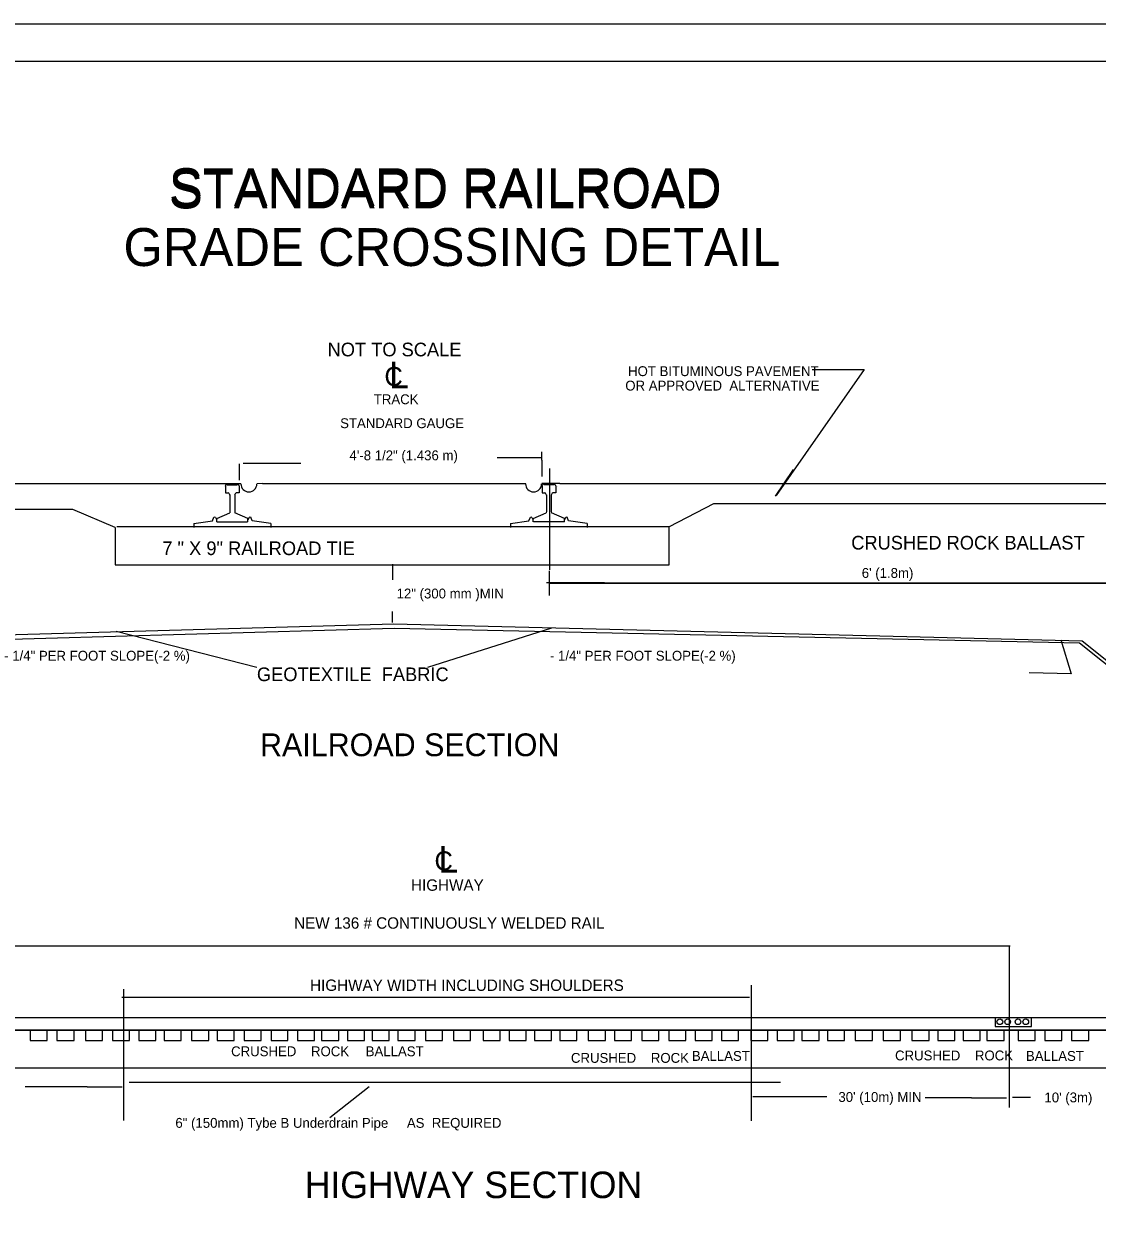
# Model space of a CAD drawing. Extents: x 1100953.69 to 1100956.55, y 386728.28 to 386730.11.
# Drawn here: x 1100954.443 to 1100955.371, y 386729.073 to 386730.11 of the extents above; entities that cross this region are included whole.
import ezdxf

# ---------------------------------------------------------------- set-up
doc = ezdxf.new("R2010")
doc.units = 0
for name, color, linetype in [('BORDER', 7, 'Continuous'), ('Level 1', 7, 'Continuous'), ('Level 33', 7, 'Continuous'), ('ORIG TOPO TEXT', 7, 'Continuous'), ('PLOT BOUNDARY', 7, 'Continuous')]:
    doc.layers.add(name, color=color, linetype=linetype)

msp = doc.modelspace()

# ---------------------------------------------------------------- linework, layer by layer
at = {"layer": 'BORDER'}
msp.add_line((1100956.4931, 386730.0776), (1100953.8264, 386730.0776), dxfattribs=at)
at = {"layer": 'Level 1'}
for p, q in [((1100954.5215, 386729.6745), (1100954.4849, 386729.69)), ((1100954.644, 386729.5534), (1100954.5223, 386729.5846)), ((1100954.7917, 386729.5536), (1100954.8992, 386729.5878)), ((1100954.2952, 386729.3127), (1100955.2955, 386729.3127)), ((1100955.0714, 386729.2788), (1100955.0714, 386729.1613)), ((1100954.5271, 386729.2684), (1100955.07, 386729.2684)), ((1100954.5286, 386729.2752), (1100954.5286, 386729.1615)), ((1100953.8943, 386729.2506), (1100955.7055, 386729.2506)), ((1100954.5336, 386729.1948), (1100955.0969, 386729.1948)), ((1100954.4973, 386729.1908), (1100954.4437, 386729.1908)), ((1100954.7412, 386729.1907), (1100954.707, 386729.1638)), ((1100955.2621, 386729.1812), (1100955.2218, 386729.1812))]:
    msp.add_line(p, q, dxfattribs=at)
for points in [[(1100954.4849, 386729.69), (1100953.8539, 386729.69), (1100953.8539, 386729.7126), (1100953.8539, 386729.7126), (1100954.6144, 386729.7126)], [(1100954.5215, 386729.6745), (1100954.5215, 386729.6423), (1100955.0005, 386729.6423), (1100955.0005, 386729.6749), (1100954.523, 386729.6749)], [(1100955.4278, 386729.5793), (1100955.395, 386729.5465), (1100955.3578, 386729.5763), (1100955.3578, 386729.5763), (1100954.7625, 386729.591), (1100954.1599, 386729.574), (1100954.1361, 386729.5502), (1100954.1075, 386729.5787)], [(1100954.1044, 386729.5735), (1100954.1351, 386729.5442), (1100954.1598, 386729.5701), (1100954.7626, 386729.5873), (1100955.3554, 386729.5746), (1100955.3951, 386729.5429), (1100955.4313, 386729.5776), (1100955.4313, 386729.5776), (1100955.4313, 386729.5776), (1100955.4313, 386729.5776)], [(1100955.7055, 386729.2398), (1100953.8939, 386729.2398), (1100953.8939, 386729.2503)], [(1100953.8943, 386729.2398), (1100953.8943, 386729.2506), (1100953.8943, 386729.2506), (1100955.7062, 386729.2506), (1100955.7062, 386729.2398)], [(1100955.2824, 386729.2507), (1100955.2824, 386729.2429), (1100955.3138, 386729.2429), (1100955.3138, 386729.2506)], [(1100953.8943, 386729.2398), (1100953.8943, 386729.2398), (1100955.7055, 386729.2398)], [(1100954.4478, 386729.2398), (1100954.4478, 386729.2308), (1100954.4626, 386729.2308), (1100954.4626, 386729.2398)], [(1100954.4711, 386729.2398), (1100954.4711, 386729.2308), (1100954.4859, 386729.2308), (1100954.4859, 386729.2398)], [(1100954.4711, 386729.2398), (1100954.4711, 386729.2308), (1100954.4859, 386729.2308), (1100954.4859, 386729.2398)], [(1100954.4957, 386729.2398), (1100954.4957, 386729.2308), (1100954.5105, 386729.2308), (1100954.5105, 386729.2398)], [(1100954.519, 386729.2398), (1100954.519, 386729.2308), (1100954.5338, 386729.2308), (1100954.5338, 386729.2398)], [(1100954.5418, 386729.2398), (1100954.5418, 386729.2308), (1100954.5566, 386729.2308), (1100954.5566, 386729.2398)], [(1100954.5638, 386729.2398), (1100954.5638, 386729.2308), (1100954.5785, 386729.2308), (1100954.5785, 386729.2398)], [(1100954.5875, 386729.2398), (1100954.5875, 386729.2308), (1100954.6023, 386729.2308), (1100954.6023, 386729.2398)], [(1100954.6096, 386729.2398), (1100954.6096, 386729.2308), (1100954.6244, 386729.2308), (1100954.6244, 386729.2398)], [(1100954.6329, 386729.2398), (1100954.6329, 386729.2308), (1100954.6477, 386729.2308), (1100954.6477, 386729.2398)], [(1100954.6562, 386729.2398), (1100954.6562, 386729.2308), (1100954.6709, 386729.2308), (1100954.6709, 386729.2398)], [(1100954.679, 386729.2398), (1100954.679, 386729.2308), (1100954.6938, 386729.2308), (1100954.6938, 386729.2398)], [(1100954.7, 386729.2398), (1100954.7, 386729.2308), (1100954.7148, 386729.2308), (1100954.7148, 386729.2398)], [(1100954.7224, 386729.2398), (1100954.7224, 386729.2308), (1100954.7372, 386729.2308), (1100954.7372, 386729.2398)], [(1100954.7436, 386729.2398), (1100954.7436, 386729.2308), (1100954.7584, 386729.2308), (1100954.7584, 386729.2398)], [(1100954.766, 386729.2398), (1100954.766, 386729.2308), (1100954.7808, 386729.2308), (1100954.7808, 386729.2398)], [(1100954.7898, 386729.2398), (1100954.7898, 386729.2308), (1100954.8045, 386729.2308), (1100954.8045, 386729.2398)], [(1100954.8139, 386729.2398), (1100954.8139, 386729.2308), (1100954.8287, 386729.2308), (1100954.8287, 386729.2398)], [(1100954.8397, 386729.2398), (1100954.8397, 386729.2308), (1100954.8545, 386729.2308), (1100954.8545, 386729.2398)], [(1100954.8621, 386729.2398), (1100954.8621, 386729.2308), (1100954.8769, 386729.2308), (1100954.8769, 386729.2398)], [(1100954.884, 386729.2398), (1100954.884, 386729.2308), (1100954.8988, 386729.2308), (1100954.8988, 386729.2398)], [(1100954.906, 386729.2398), (1100954.906, 386729.2308), (1100954.9208, 386729.2308), (1100954.9208, 386729.2398)], [(1100954.9306, 386729.2398), (1100954.9306, 386729.2308), (1100954.9454, 386729.2308), (1100954.9454, 386729.2398)], [(1100954.9532, 386729.2398), (1100954.9532, 386729.2308), (1100954.9679, 386729.2308), (1100954.9679, 386729.2398)], [(1100954.9769, 386729.2398), (1100954.9769, 386729.2308), (1100954.9917, 386729.2308), (1100954.9917, 386729.2398)], [(1100955.0002, 386729.2398), (1100955.0002, 386729.2308), (1100955.015, 386729.2308), (1100955.015, 386729.2398)], [(1100955.023, 386729.2398), (1100955.023, 386729.2308), (1100955.0378, 386729.2308), (1100955.0378, 386729.2398)], [(1100955.0458, 386729.2398), (1100955.0458, 386729.2308), (1100955.0606, 386729.2308), (1100955.0606, 386729.2398)], [(1100955.0711, 386729.2398), (1100955.0711, 386729.2308), (1100955.0859, 386729.2308), (1100955.0859, 386729.2398)], [(1100955.0939, 386729.2398), (1100955.0939, 386729.2308), (1100955.1087, 386729.2308), (1100955.1087, 386729.2398)], [(1100955.1154, 386729.2398), (1100955.1154, 386729.2308), (1100955.1302, 386729.2308), (1100955.1302, 386729.2398)], [(1100955.1374, 386729.2398), (1100955.1374, 386729.2308), (1100955.1521, 386729.2308), (1100955.1521, 386729.2398)], [(1100955.1615, 386729.2398), (1100955.1615, 386729.2308), (1100955.1763, 386729.2308), (1100955.1763, 386729.2398)], [(1100955.1857, 386729.2398), (1100955.1857, 386729.2308), (1100955.2005, 386729.2308), (1100955.2005, 386729.2398)], [(1100955.2105, 386729.2398), (1100955.2105, 386729.2308), (1100955.2253, 386729.2308), (1100955.2253, 386729.2398)], [(1100955.2329, 386729.2398), (1100955.2329, 386729.2308), (1100955.2477, 386729.2308), (1100955.2477, 386729.2398)], [(1100955.2548, 386729.2398), (1100955.2548, 386729.2308), (1100955.2696, 386729.2308), (1100955.2696, 386729.2398)], [(1100955.2754, 386729.2398), (1100955.2754, 386729.2308), (1100955.2902, 386729.2308), (1100955.2902, 386729.2398)], [(1100955.3023, 386729.2398), (1100955.3023, 386729.2308), (1100955.3171, 386729.2308), (1100955.3171, 386729.2398)], [(1100955.3253, 386729.2398), (1100955.3253, 386729.2308), (1100955.3401, 386729.2308), (1100955.3401, 386729.2398)], [(1100955.3486, 386729.2398), (1100955.3486, 386729.2308), (1100955.3634, 386729.2308), (1100955.3634, 386729.2398)], [(1100954.1987, 386729.2072), (1100955.4041, 386729.2072), (1100955.7053, 386729.2275)]]:
    msp.add_lwpolyline(points, dxfattribs=at)
msp.add_lwpolyline([(1100954.5282, 386729.2505), (1100954.5282, 386729.2505)], close=True, dxfattribs=at)
for centre in [(1100955.2865, 386729.247), (1100955.2933, 386729.247), (1100955.3022, 386729.247), (1100955.3089, 386729.247)]:
    msp.add_circle(centre, 0.00247, dxfattribs=at)
at = {"layer": 'Level 33'}
for p, q in [((1100954.8905, 386729.7326), (1100954.8905, 386729.74)), ((1100954.6288, 386729.7294), (1100954.6288, 386729.7154)), ((1100954.8905, 386729.7326), (1100954.8905, 386729.7187)), ((1100954.897, 386729.7256), (1100954.897, 386729.6378)), ((1100954.6144, 386729.7126), (1100954.6301, 386729.7126)), ((1100954.6182, 386729.7115), (1100954.6268, 386729.7115)), ((1100954.906, 386729.7126), (1100954.8904, 386729.7126)), ((1100954.901, 386729.7115), (1100954.8924, 386729.7115)), ((1100954.906, 386729.7126), (1100955.6632, 386729.7126)), ((1100954.6206, 386729.7026), (1100954.6206, 386729.6883)), ((1100954.6206, 386729.7026), (1100954.6206, 386729.6883)), ((1100954.6248, 386729.7026), (1100954.6248, 386729.6883)), ((1100954.6248, 386729.7026), (1100954.6248, 386729.6883)), ((1100954.8944, 386729.7026), (1100954.8944, 386729.6883)), ((1100954.8944, 386729.7026), (1100954.8944, 386729.6883)), ((1100954.8986, 386729.7026), (1100954.8986, 386729.6883)), ((1100954.8986, 386729.7026), (1100954.8986, 386729.6883)), ((1100955.0388, 386729.6949), (1100955.0005, 386729.6749)), ((1100955.6632, 386729.6949), (1100955.0388, 386729.6949)), ((1100954.6083, 386729.6831), (1100954.6082, 386729.6832)), ((1100954.6083, 386729.6831), (1100954.6093, 386729.681)), ((1100954.6206, 386729.6883), (1100954.6205, 386729.6871)), ((1100954.6206, 386729.6883), (1100954.6205, 386729.6871)), ((1100954.6248, 386729.6883), (1100954.6249, 386729.6871)), ((1100954.6248, 386729.6883), (1100954.6249, 386729.6871)), ((1100954.6373, 386729.6831), (1100954.6363, 386729.681)), ((1100954.6373, 386729.6831), (1100954.6374, 386729.6832)), ((1100954.8819, 386729.6831), (1100954.8818, 386729.6832)), ((1100954.8819, 386729.6831), (1100954.8829, 386729.681)), ((1100954.8944, 386729.6883), (1100954.8943, 386729.6871)), ((1100954.8944, 386729.6883), (1100954.8943, 386729.6871)), ((1100954.8986, 386729.6883), (1100954.8987, 386729.6871)), ((1100954.8986, 386729.6883), (1100954.8987, 386729.6871)), ((1100954.9109, 386729.6831), (1100954.9099, 386729.681)), ((1100954.9109, 386729.6831), (1100954.911, 386729.6832)), ((1100954.5896, 386729.678), (1100954.5896, 386729.6745)), ((1100954.6093, 386729.6794), (1100954.6359, 386729.6794)), ((1100954.656, 386729.678), (1100954.656, 386729.6745)), ((1100954.8632, 386729.678), (1100954.8632, 386729.6745)), ((1100954.9099, 386729.6794), (1100954.8833, 386729.6794)), ((1100954.9296, 386729.678), (1100954.9296, 386729.6745)), ((1100954.8967, 386729.637), (1100954.8967, 386729.6156)), ((1100954.8967, 386729.6263), (1100955.4288, 386729.6263)), ((1100954.9025, 386729.6266), (1100955.4346, 386729.6266))]:
    msp.add_line(p, q, dxfattribs=at)
for points in [[(1100955.1241, 386729.8112), (1100955.1691, 386729.8112), (1100955.0931, 386729.7021)], [(1100954.6168, 386729.7104), (1100954.6168, 386729.7045), (1100954.6193, 386729.7045)], [(1100954.6168, 386729.7104), (1100954.6168, 386729.7045), (1100954.6193, 386729.7045)], [(1100954.6286, 386729.7104), (1100954.6286, 386729.7045), (1100954.6262, 386729.7045)], [(1100954.6286, 386729.7104), (1100954.6286, 386729.7045), (1100954.6262, 386729.7045)], [(1100954.8906, 386729.7104), (1100954.8906, 386729.7045), (1100954.8931, 386729.7045)], [(1100954.8906, 386729.7104), (1100954.8906, 386729.7045), (1100954.8931, 386729.7045)], [(1100954.9024, 386729.7104), (1100954.9024, 386729.7045), (1100954.8999, 386729.7045)], [(1100954.9024, 386729.7104), (1100954.9024, 386729.7045), (1100954.8999, 386729.7045)], [(1100954.5896, 386729.678), (1100954.6057, 386729.6803), (1100954.6069, 386729.6833)], [(1100954.6093, 386729.6794), (1100954.6093, 386729.6822), (1100954.6205, 386729.6871)], [(1100954.6093, 386729.6794), (1100954.6093, 386729.6822), (1100954.6205, 386729.6871)], [(1100954.6362, 386729.6794), (1100954.6362, 386729.6822), (1100954.6249, 386729.6871)], [(1100954.6362, 386729.6794), (1100954.6362, 386729.6822), (1100954.6249, 386729.6871)], [(1100954.656, 386729.678), (1100954.6399, 386729.6803), (1100954.6387, 386729.6833)], [(1100954.8632, 386729.678), (1100954.8793, 386729.6803), (1100954.8805, 386729.6833)], [(1100954.883, 386729.6794), (1100954.883, 386729.6822), (1100954.8943, 386729.6871)], [(1100954.883, 386729.6794), (1100954.883, 386729.6822), (1100954.8943, 386729.6871)], [(1100954.9099, 386729.6794), (1100954.9099, 386729.6822), (1100954.8987, 386729.6871)], [(1100954.9099, 386729.6794), (1100954.9099, 386729.6822), (1100954.8987, 386729.6871)], [(1100954.9296, 386729.678), (1100954.9135, 386729.6803), (1100954.9123, 386729.6833)], [(1100955.3392, 386729.5772), (1100955.3483, 386729.548), (1100955.3118, 386729.5489)]]:
    msp.add_lwpolyline(points, dxfattribs=at)
for points in [[(1100954.6083, 386729.6831), (1100954.6083, 386729.6831)], [(1100954.6083, 386729.6831), (1100954.6083, 386729.6831)], [(1100954.6373, 386729.6831), (1100954.6373, 386729.6831)], [(1100954.6373, 386729.6831), (1100954.6373, 386729.6831)], [(1100954.8819, 386729.6831), (1100954.8819, 386729.6831)], [(1100954.8819, 386729.6831), (1100954.8819, 386729.6831)], [(1100954.9109, 386729.6831), (1100954.9109, 386729.6831)], [(1100954.9109, 386729.6831), (1100954.9109, 386729.6831)]]:
    msp.add_lwpolyline(points, close=True, dxfattribs=at)
for centre, radius, start, end in [((1100954.6179, 386729.7104), 0.00114, 66.8455, 180), ((1100954.6179, 386729.7104), 0.00114, 66.8455, 180), ((1100954.6179, 386729.7104), 0.00114, 180, 191.1791), ((1100954.6179, 386729.7104), 0.00114, 180, 191.1791), ((1100954.6177, 386729.7019), 0.00298, 9.937, 58.7108), ((1100954.6177, 386729.7019), 0.00298, 9.937, 58.7108), ((1100954.6277, 386729.7019), 0.00298, 121.2892, 170.063), ((1100954.6277, 386729.7019), 0.00298, 121.2892, 170.063), ((1100954.6275, 386729.7104), 0.00114, 0, 113.1545), ((1100954.6275, 386729.7104), 0.00114, 0, 113.1545), ((1100954.6275, 386729.7104), 0.00114, 348.8209, 0), ((1100954.6275, 386729.7104), 0.00114, 348.8209, 0), ((1100954.6371, 386729.7122), 0.00695, 180, 0), ((1100954.8833, 386729.7122), 0.00695, 180, 0), ((1100954.8917, 386729.7104), 0.00114, 66.8455, 180), ((1100954.8917, 386729.7104), 0.00114, 66.8455, 180), ((1100954.8917, 386729.7104), 0.00114, 180, 191.1791), ((1100954.8917, 386729.7104), 0.00114, 180, 191.1791), ((1100954.8915, 386729.7019), 0.00298, 9.937, 58.7108), ((1100954.8915, 386729.7019), 0.00298, 9.937, 58.7108), ((1100954.9015, 386729.7019), 0.00298, 121.2892, 170.063), ((1100954.9015, 386729.7019), 0.00298, 121.2892, 170.063), ((1100954.9013, 386729.7104), 0.00114, 0, 113.1545), ((1100954.9013, 386729.7104), 0.00114, 0, 113.1545), ((1100954.9013, 386729.7104), 0.00114, 348.8209, 0), ((1100954.9013, 386729.7104), 0.00114, 348.8209, 0), ((1100954.9025, 386729.7104), 0.00114, 348.8209, 0), ((1100954.6075, 386729.6825), 0.000953, 45.7327, 135.7327), ((1100954.638, 386729.6825), 0.000953, 44.2673, 134.2673), ((1100954.8812, 386729.6825), 0.000953, 45.7327, 135.7327), ((1100954.9117, 386729.6825), 0.000953, 44.2673, 134.2673)]:
    msp.add_arc(centre, radius, start, end, dxfattribs=at)
at = {"layer": 'ORIG TOPO TEXT'}
for p, q in [((1100954.8519, 386729.7349), (1100954.8904, 386729.7349)), ((1100954.8519, 386729.7349), (1100954.8904, 386729.7349)), ((1100954.6821, 386729.7299), (1100954.6321, 386729.7299)), ((1100955.1079, 386729.7245), (1100955.0923, 386729.7016)), ((1100954.6489, 386729.7124), (1100954.6441, 386729.7122)), ((1100954.7617, 386729.6293), (1100954.7617, 386729.6427)), ((1100954.9446, 386729.6266), (1100954.8946, 386729.6266)), ((1100954.761, 386729.6019), (1100954.761, 386729.5922)), ((1100955.2945, 386729.3121), (1100955.2945, 386729.173)), ((1100954.4973, 386729.1908), (1100954.5274, 386729.1908)), ((1100955.1369, 386729.1821), (1100955.0728, 386729.1821)), ((1100955.2621, 386729.1812), (1100955.2922, 386729.1812)), ((1100955.3131, 386729.1814), (1100955.2974, 386729.1814))]:
    msp.add_line(p, q, dxfattribs=at)
msp.add_lwpolyline([(1100954.6489, 386729.7124), (1100954.8765, 386729.7124)], dxfattribs=at)
at = {"layer": 'PLOT BOUNDARY'}
msp.add_lwpolyline([(1100953.6916, 386728.2766), (1100956.5249, 386728.2766), (1100956.5249, 386730.1099), (1100953.6916, 386730.1099)], close=True, dxfattribs=at)

# ---------------------------------------------------------------- texts
at = {"layer": 'ORIG TOPO TEXT'}
for s, height, p in [('STANDARD RAILROAD', 0.032807, (1100954.568, 386729.9524)), ('STANDARD RAILROAD', 0.032807, (1100954.568, 386729.9504)), ('GRADE CROSSING DETAIL', 0.032807, (1100954.5286, 386729.9006)), ('GRADE CROSSING DETAIL', 0.032807, (1100954.5286, 386729.9006)), ('NOT TO SCALE', 0.011811, (1100954.7051, 386729.8225)), ('L', 0.023, (1100954.7583, 386729.7949)), ('C', 0.0164, (1100954.7543, 386729.7969)), ('HOT BITUMINOUS PAVEMENT', 0.008531, (1100954.965, 386729.8054)), ('OR APPROVED  ALTERNATIVE', 0.008531, (1100954.9626, 386729.7929)), ('TRACK', 0.00853, (1100954.7451, 386729.7811)), ('STANDARD GAUGE', 0.008531, (1100954.716, 386729.7604)), (' 4\'-8 1/2" (1.436 m)', 0.008531, (1100954.7209, 386729.7326)), ('7 " X 9" RAILROAD TIE', 0.011811, (1100954.5622, 386729.6506)), ('CRUSHED ROCK BALLAST', 0.011811, (1100955.158, 386729.6554)), ("6' (1.8m)", 0.00853, (1100955.1671, 386729.6309)), ('12" (300 mm )MIN', 0.008531, (1100954.7648, 386729.6131)), ('     - 1/4" PER FOOT SLOPE(-2 %)', 0.008531, (1100954.4096, 386729.5593)), ('     - 1/4" PER FOOT SLOPE(-2 %)', 0.008531, (1100954.8816, 386729.5593)), ('GEOTEXTILE  FABRIC', 0.011811, (1100954.644, 386729.5416)), ('RAILROAD SECTION', 0.019685, (1100954.6467, 386729.4767)), ('C', 0.0164, (1100954.7976, 386729.378)), ('L', 0.023, (1100954.8009, 386729.376)), ('HIGHWAY', 0.00984, (1100954.7773, 386729.3603)), ('NEW 136 # CONTINUOUSLY WELDED RAIL', 0.009843, (1100954.6762, 386729.3275)), ('HIGHWAY WIDTH INCLUDING SHOULDERS', 0.009843, (1100954.69, 386729.2737)), ('CRUSHED    ROCK', 0.008531, (1100954.6217, 386729.2172)), ('BALLAST', 0.00853, (1100954.7381, 386729.2172)), ('CRUSHED    ROCK', 0.008531, (1100954.9156, 386729.2115)), ('BALLAST', 0.00853, (1100955.0202, 386729.2132)), ('CRUSHED    ROCK', 0.008531, (1100955.1959, 386729.2136)), ('BALLAST', 0.00853, (1100955.3091, 386729.2132)), ("30' (10m) MIN", 0.008531, (1100955.1469, 386729.1777)), ("10' (3m)", 0.00853, (1100955.3251, 386729.1773)), ('6" (150mm) Tybe B Underdrain Pipe  ', 0.008531, (1100954.5735, 386729.1553)), ('AS  REQUIRED', 0.008531, (1100954.7737, 386729.1553)), ('HIGHWAY SECTION', 0.022965, (1100954.6854, 386729.0945)), ('HIGHWAY SECTION', 0.022965, (1100954.6854, 386729.0945))]:
    msp.add_text(s, height=height, dxfattribs=at).set_placement(p)

doc.saveas('drawing.dxf')
